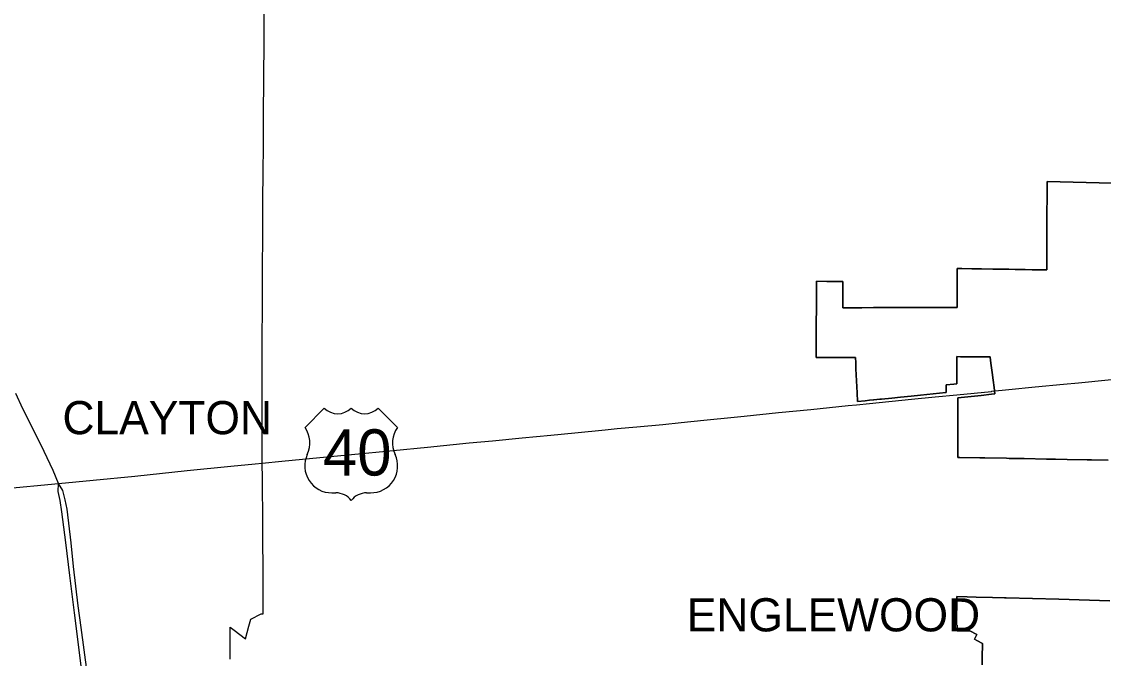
# Model space of a CAD drawing. Extents: x 0 to 34, y 0 to 22.
# Drawn here: x 4.4592 to 4.7212, y 15.7932 to 15.9476 of the extents above; entities that cross this region are included whole.
import ezdxf

# ---------------------------------------------------------------- set-up
doc = ezdxf.new("R2010")
doc.units = 0
for name, color, linetype in [('GM_X_Corporation', 7, 'Continuous'), ('GM_X_Corporation_Text', 7, 'Continuous'), ('GM_X_State_Route', 7, 'Continuous'), ('GM_X_US_Location', 7, 'Continuous'), ('GM_X_US_Route', 7, 'Continuous'), ('GM_X_US_Shield', 7, 'Continuous')]:
    doc.layers.add(name, color=color, linetype=linetype)

msp = doc.modelspace()

# ---------------------------------------------------------------- linework, layer by layer
at = {"layer": 'GM_X_Corporation'}
for points in [[(4.509726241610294, 15.793017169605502), (4.509716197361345, 15.794641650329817), (4.5097080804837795, 15.795954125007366), (4.509688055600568, 15.799192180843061), (4.509677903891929, 15.800833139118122), (4.510646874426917, 15.80009527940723), (4.513431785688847, 15.797974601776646), (4.5142712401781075, 15.801067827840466), (4.514736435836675, 15.802782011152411), (4.517228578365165, 15.80401493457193), (4.517710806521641, 15.804016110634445), (4.517710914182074, 15.804151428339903), (4.517709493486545, 15.804630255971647), (4.517699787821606, 15.807912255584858), (4.517699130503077, 15.808133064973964), (4.51769517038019, 15.809471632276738), (4.517673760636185, 15.81670944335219), (4.517672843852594, 15.817282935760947), (4.517672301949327, 15.81735647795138), (4.517655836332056, 15.819581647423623), (4.517641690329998, 15.821492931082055), (4.517636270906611, 15.822225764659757), (4.517621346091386, 15.82424240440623), (4.517612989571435, 15.82537208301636), (4.5175259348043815, 15.837136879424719), (4.517503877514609, 15.840117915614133), (4.5175002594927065, 15.840606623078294), (4.517500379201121, 15.840635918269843), (4.5174993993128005, 15.841239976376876), (4.517497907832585, 15.842158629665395), (4.517491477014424, 15.8461065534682), (4.517487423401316, 15.84860105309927), (4.517482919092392, 15.851368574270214), (4.517482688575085, 15.851509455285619), (4.51747875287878, 15.853929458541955), (4.517477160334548, 15.854908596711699), (4.517471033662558, 15.858674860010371), (4.517470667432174, 15.858895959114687), (4.517469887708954, 15.8593781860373), (4.517466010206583, 15.86175995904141), (4.517462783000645, 15.863741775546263), (4.517461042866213, 15.864812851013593), (4.517460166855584, 15.865350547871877), (4.5174602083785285, 15.865377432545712), (4.517460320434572, 15.865450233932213), (4.517471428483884, 15.86784446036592), (4.5174811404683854, 15.869938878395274), (4.517488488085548, 15.871521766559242), (4.5174935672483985, 15.872616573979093), (4.51749410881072, 15.872733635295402), (4.517510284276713, 15.876221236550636), (4.517529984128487, 15.880468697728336), (4.517545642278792, 15.883845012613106), (4.517554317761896, 15.88571430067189), (4.517559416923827, 15.886813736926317), (4.517563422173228, 15.887677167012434), (4.517563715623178, 15.887741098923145), (4.517564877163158, 15.88784580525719), (4.517565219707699, 15.887876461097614), (4.51756956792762, 15.888810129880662), (4.517576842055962, 15.89010945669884), (4.517594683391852, 15.893296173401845), (4.517647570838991, 15.902744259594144), (4.517652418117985, 15.903610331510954), (4.517655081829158, 15.904085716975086), (4.517671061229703, 15.906940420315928), (4.517678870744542, 15.908335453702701), (4.5177715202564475, 15.920094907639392), (4.517808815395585, 15.924827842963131), (4.517950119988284, 15.942761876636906), (4.517950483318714, 15.942916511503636), (4.517988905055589, 15.950246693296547)], [(4.722420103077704, 15.84125548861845), (4.718355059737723, 15.841334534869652), (4.717294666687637, 15.841355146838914), (4.712477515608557, 15.841448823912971), (4.712440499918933, 15.841449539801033), (4.709653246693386, 15.841503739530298), (4.707495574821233, 15.841545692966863), (4.702085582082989, 15.841650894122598), (4.700604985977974, 15.841679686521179), (4.699983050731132, 15.841691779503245), (4.698512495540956, 15.84172037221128), (4.698403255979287, 15.841722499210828), (4.697781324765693, 15.841734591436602), (4.6925126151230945, 15.841837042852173), (4.6913604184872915, 15.841859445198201), (4.686508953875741, 15.841953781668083), (4.685971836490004, 15.841964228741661), (4.685974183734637, 15.843864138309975), (4.68597219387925, 15.84422798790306), (4.685971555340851, 15.844343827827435), (4.685972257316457, 15.844765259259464), (4.685972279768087, 15.844779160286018), (4.685974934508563, 15.846386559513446), (4.685975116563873, 15.846473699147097), (4.6859806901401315, 15.84913856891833), (4.6859815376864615, 15.849827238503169), (4.6859852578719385, 15.852836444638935), (4.685988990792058, 15.855863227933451), (4.685989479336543, 15.856260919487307), (4.685989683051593, 15.8564212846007), (4.6916416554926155, 15.856988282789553), (4.694117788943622, 15.857236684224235), (4.694989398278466, 15.857324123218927), (4.694780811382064, 15.858918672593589), (4.694553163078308, 15.860658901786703), (4.694396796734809, 15.861854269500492), (4.694387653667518, 15.861924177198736), (4.694239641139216, 15.863055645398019), (4.6940840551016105, 15.864245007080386), (4.693927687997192, 15.865440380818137), (4.693812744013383, 15.866312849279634), (4.693705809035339, 15.866313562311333), (4.692894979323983, 15.866318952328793), (4.692775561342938, 15.866319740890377), (4.691689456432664, 15.866326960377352), (4.691570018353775, 15.86632775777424), (4.690907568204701, 15.866332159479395), (4.6900566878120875, 15.866337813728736), (4.689945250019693, 15.866338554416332), (4.689663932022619, 15.866340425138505), (4.689337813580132, 15.866342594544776), (4.686881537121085, 15.86635891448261), (4.686659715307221, 15.86636039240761), (4.685739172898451, 15.866377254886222), (4.685729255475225, 15.859781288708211), (4.685008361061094, 15.859708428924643), (4.683173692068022, 15.859523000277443), (4.683165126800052, 15.857913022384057), (4.683163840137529, 15.857670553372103), (4.683051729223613, 15.857659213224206), (4.676954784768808, 15.85704280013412), (4.6747094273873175, 15.856815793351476), (4.67469267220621, 15.856814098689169), (4.67212600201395, 15.856554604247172), (4.66999573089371, 15.856339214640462), (4.6675257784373, 15.856089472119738), (4.667136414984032, 15.856050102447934), (4.665617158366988, 15.855896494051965), (4.665609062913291, 15.855895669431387), (4.665607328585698, 15.855895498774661), (4.66559756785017, 15.855894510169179), (4.665587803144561, 15.855893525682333), (4.6655780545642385, 15.855892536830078), (4.664612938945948, 15.8557949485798), (4.664562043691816, 15.855789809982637), (4.663577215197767, 15.85569023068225), (4.663567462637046, 15.85568924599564), (4.663557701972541, 15.855688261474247), (4.663547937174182, 15.855687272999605), (4.66353816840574, 15.855686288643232), (4.661691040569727, 15.855499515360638), (4.661592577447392, 15.857578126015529), (4.661524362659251, 15.85902534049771), (4.6614560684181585, 15.86047419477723), (4.661454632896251, 15.860504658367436), (4.6613869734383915, 15.861940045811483), (4.661319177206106, 15.86337824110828), (4.6612506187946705, 15.864832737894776), (4.661186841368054, 15.866185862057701), (4.660272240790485, 15.866180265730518), (4.659840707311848, 15.866177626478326), (4.659466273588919, 15.866175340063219), (4.659070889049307, 15.866172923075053), (4.65794508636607, 15.866166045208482), (4.65714911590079, 15.866161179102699), (4.65668844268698, 15.866158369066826), (4.655402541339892, 15.866150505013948), (4.6536903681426, 15.866140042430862), (4.653088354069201, 15.866136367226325), (4.651654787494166, 15.866127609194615), (4.651662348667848, 15.867439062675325), (4.651676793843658, 15.869946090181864), (4.651678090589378, 15.870170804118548), (4.651684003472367, 15.871196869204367), (4.651698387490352, 15.873694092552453), (4.651706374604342, 15.875079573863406), (4.651711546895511, 15.875977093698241), (4.6517148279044, 15.876546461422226), (4.651723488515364, 15.878049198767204), (4.651730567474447, 15.879278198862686), (4.651736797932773, 15.880358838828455), (4.651741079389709, 15.8811019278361), (4.651743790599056, 15.881572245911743), (4.651752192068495, 15.883030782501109), (4.651755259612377, 15.883562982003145), (4.651761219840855, 15.88458774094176), (4.651761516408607, 15.884638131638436), (4.654242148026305, 15.884612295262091), (4.656624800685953, 15.884587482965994), (4.656946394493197, 15.88458413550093), (4.658161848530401, 15.884571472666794), (4.658148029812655, 15.882644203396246), (4.658144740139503, 15.882184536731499), (4.658133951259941, 15.880680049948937), (4.658121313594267, 15.87891677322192), (4.658116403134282, 15.878232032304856), (4.6583687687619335, 15.878232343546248), (4.661063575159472, 15.878235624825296), (4.661903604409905, 15.878236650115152), (4.662526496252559, 15.878237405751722), (4.662742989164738, 15.878237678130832), (4.6655903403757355, 15.878241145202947), (4.666466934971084, 15.878242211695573), (4.668127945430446, 15.878244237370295), (4.66940609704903, 15.878250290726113), (4.6720530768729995, 15.878262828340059), (4.673564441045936, 15.878269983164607), (4.673640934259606, 15.878270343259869), (4.674496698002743, 15.878274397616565), (4.6761505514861, 15.878279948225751), (4.677249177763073, 15.878283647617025), (4.677696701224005, 15.878285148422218), (4.679169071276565, 15.878290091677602), (4.6807055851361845, 15.878295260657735), (4.681147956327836, 15.878296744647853), (4.682150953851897, 15.878300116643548), (4.683435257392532, 15.878304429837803), (4.684993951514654, 15.878309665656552), (4.685816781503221, 15.878311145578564), (4.685800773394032, 15.887731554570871), (4.686604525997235, 15.887720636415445), (4.6869696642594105, 15.887714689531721), (4.689419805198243, 15.887674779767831), (4.689811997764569, 15.887668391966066), (4.6913536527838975, 15.887643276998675), (4.691750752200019, 15.887636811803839), (4.694475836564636, 15.887592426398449), (4.6948696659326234, 15.88758600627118), (4.697886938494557, 15.887536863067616), (4.698309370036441, 15.887529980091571), (4.699888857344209, 15.88750386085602), (4.7002981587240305, 15.887497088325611), (4.701899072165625, 15.887470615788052), (4.702307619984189, 15.887463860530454), (4.704012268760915, 15.887435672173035), (4.704424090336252, 15.887428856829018), (4.704816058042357, 15.887422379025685), (4.705227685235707, 15.887415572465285), (4.707558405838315, 15.88740632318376), (4.70758112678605, 15.89733271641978), (4.707635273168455, 15.908818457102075), (4.726492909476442, 15.90830667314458)], [(4.7264932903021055, 15.908306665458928), (4.707635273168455, 15.908818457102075), (4.70758112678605, 15.89733271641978), (4.707558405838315, 15.88740632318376), (4.707534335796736, 15.887406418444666), (4.705227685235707, 15.887415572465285), (4.704816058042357, 15.887422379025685), (4.704424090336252, 15.887428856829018), (4.704012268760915, 15.887435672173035), (4.702307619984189, 15.887463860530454), (4.701899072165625, 15.887470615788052), (4.7002981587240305, 15.887497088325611), (4.699888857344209, 15.88750386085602), (4.698309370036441, 15.887529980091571), (4.697886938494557, 15.887536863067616), (4.6948696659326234, 15.88758600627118), (4.694475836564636, 15.887592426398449), (4.691750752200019, 15.887636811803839), (4.6913536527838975, 15.887643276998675), (4.689811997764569, 15.887668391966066), (4.689419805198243, 15.887674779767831), (4.6869696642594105, 15.887714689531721), (4.686604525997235, 15.887720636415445), (4.68580076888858, 15.8877337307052), (4.685816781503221, 15.878311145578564), (4.684993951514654, 15.878309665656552), (4.683435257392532, 15.878304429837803), (4.682150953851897, 15.878300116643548), (4.681147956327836, 15.878296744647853), (4.6807055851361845, 15.878295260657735), (4.679169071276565, 15.878290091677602), (4.677696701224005, 15.878285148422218), (4.677249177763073, 15.878283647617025), (4.6761505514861, 15.878279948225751), (4.674496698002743, 15.878274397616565), (4.673640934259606, 15.878270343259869), (4.673564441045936, 15.878269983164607), (4.6720530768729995, 15.878262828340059), (4.66940609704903, 15.878250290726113), (4.668127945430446, 15.878244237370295), (4.666466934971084, 15.878242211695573), (4.6655903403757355, 15.878241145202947), (4.662742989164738, 15.878237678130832), (4.662526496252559, 15.878237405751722), (4.661903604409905, 15.878236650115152), (4.661063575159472, 15.878235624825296), (4.6583687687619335, 15.878232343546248), (4.658116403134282, 15.878232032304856), (4.658121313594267, 15.87891677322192), (4.658133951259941, 15.880680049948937), (4.658144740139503, 15.882184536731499), (4.658148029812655, 15.882644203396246), (4.658161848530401, 15.884571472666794), (4.656946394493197, 15.88458413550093), (4.656624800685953, 15.884587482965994), (4.654242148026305, 15.884612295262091), (4.651761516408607, 15.884638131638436), (4.651761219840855, 15.88458774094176), (4.651755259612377, 15.883562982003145), (4.651752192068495, 15.883030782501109), (4.651743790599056, 15.881572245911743), (4.651741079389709, 15.8811019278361), (4.651736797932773, 15.880358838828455), (4.651730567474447, 15.879278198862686), (4.651723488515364, 15.878049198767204), (4.6517148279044, 15.876546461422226), (4.651711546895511, 15.875977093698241), (4.651706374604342, 15.875079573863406), (4.651698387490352, 15.873694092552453), (4.651684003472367, 15.871196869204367), (4.651678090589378, 15.870170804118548), (4.651676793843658, 15.869946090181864), (4.651662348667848, 15.867439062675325), (4.651654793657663, 15.86612791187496), (4.653088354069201, 15.866136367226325), (4.6536903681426, 15.866140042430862), (4.655402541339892, 15.866150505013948), (4.65668844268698, 15.866158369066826), (4.65714911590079, 15.866161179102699), (4.65794508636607, 15.866166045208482), (4.659070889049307, 15.866172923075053), (4.659466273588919, 15.866175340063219), (4.659840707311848, 15.866177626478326), (4.660272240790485, 15.866180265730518), (4.661186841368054, 15.866185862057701), (4.6612506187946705, 15.864832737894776), (4.661319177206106, 15.86337824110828), (4.6613869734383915, 15.861940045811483), (4.6614560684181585, 15.86047419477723), (4.661524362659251, 15.85902534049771), (4.661592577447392, 15.857578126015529), (4.661690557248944, 15.855499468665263), (4.66353816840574, 15.855686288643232), (4.663547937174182, 15.855687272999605), (4.663557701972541, 15.855688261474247), (4.663567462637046, 15.85568924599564), (4.663577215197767, 15.85569023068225), (4.664562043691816, 15.855789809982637), (4.664612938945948, 15.8557949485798), (4.6655780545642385, 15.855892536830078), (4.665587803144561, 15.855893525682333), (4.66559756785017, 15.855894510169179), (4.665607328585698, 15.855895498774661), (4.665609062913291, 15.855895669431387), (4.665617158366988, 15.855896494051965), (4.667136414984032, 15.856050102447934), (4.6675257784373, 15.856089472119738), (4.66999573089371, 15.856339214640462), (4.67212600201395, 15.856554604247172), (4.67469267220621, 15.856814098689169), (4.6747094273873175, 15.856815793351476), (4.676954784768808, 15.85704280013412), (4.683051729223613, 15.857659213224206), (4.683163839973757, 15.857670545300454), (4.683165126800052, 15.857913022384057), (4.683173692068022, 15.859523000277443), (4.685008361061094, 15.859708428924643), (4.685729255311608, 15.859781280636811), (4.685738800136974, 15.866377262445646), (4.686659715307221, 15.86636039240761), (4.686881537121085, 15.86635891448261), (4.689337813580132, 15.866342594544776), (4.689663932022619, 15.866340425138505), (4.689945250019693, 15.866338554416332), (4.6900566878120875, 15.866337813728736), (4.690907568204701, 15.866332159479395), (4.691570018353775, 15.86632775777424), (4.691689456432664, 15.866326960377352), (4.692775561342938, 15.866319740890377), (4.692894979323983, 15.866318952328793), (4.693705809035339, 15.866313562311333), (4.693812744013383, 15.866312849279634), (4.693927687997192, 15.865440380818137), (4.694083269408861, 15.864251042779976), (4.694239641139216, 15.863055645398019), (4.694387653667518, 15.861924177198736), (4.694396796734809, 15.861854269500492), (4.694553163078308, 15.860658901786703), (4.694781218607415, 15.858915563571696), (4.694989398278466, 15.857324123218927), (4.694117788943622, 15.857236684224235), (4.6916416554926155, 15.856988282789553), (4.685989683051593, 15.8564212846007), (4.685989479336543, 15.856260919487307), (4.685988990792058, 15.855863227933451), (4.6859852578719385, 15.852836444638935), (4.6859815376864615, 15.849827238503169), (4.6859806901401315, 15.84913856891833), (4.685975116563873, 15.846473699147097), (4.685974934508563, 15.846386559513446), (4.685972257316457, 15.844765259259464), (4.685971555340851, 15.844343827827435), (4.68597219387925, 15.84422798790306), (4.685974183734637, 15.843864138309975), (4.685971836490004, 15.841964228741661), (4.686508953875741, 15.841953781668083), (4.6913604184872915, 15.841859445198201), (4.6925126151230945, 15.841837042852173), (4.697781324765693, 15.841734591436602), (4.698403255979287, 15.841722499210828), (4.698512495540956, 15.84172037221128), (4.699983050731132, 15.841691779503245), (4.700604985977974, 15.841679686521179), (4.702085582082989, 15.841650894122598), (4.707495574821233, 15.841545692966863), (4.709653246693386, 15.841503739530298), (4.712440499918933, 15.841449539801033), (4.712477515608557, 15.841448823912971), (4.717294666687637, 15.841355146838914), (4.718355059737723, 15.841334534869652), (4.722420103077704, 15.84125548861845)], [(4.691918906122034, 15.791652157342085), (4.691925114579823, 15.79339569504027), (4.691937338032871, 15.796827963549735), (4.690605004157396, 15.797567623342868), (4.690024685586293, 15.797889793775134), (4.69000357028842, 15.797901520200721), (4.6901109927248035, 15.798095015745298), (4.690610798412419, 15.798995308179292), (4.6889374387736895, 15.79992429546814), (4.685822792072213, 15.799935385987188), (4.685817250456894, 15.799935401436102), (4.6858239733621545, 15.801202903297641), (4.685824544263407, 15.801310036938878), (4.685687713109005, 15.801310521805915), (4.685710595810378, 15.80823819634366), (4.685768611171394, 15.808236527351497), (4.688229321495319, 15.808165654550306), (4.69041016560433, 15.808102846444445), (4.694375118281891, 15.807988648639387), (4.697277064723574, 15.807905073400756), (4.697708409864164, 15.80789265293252), (4.710497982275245, 15.807563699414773), (4.722801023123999, 15.807224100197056)], [(4.722801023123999, 15.807224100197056), (4.710497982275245, 15.807563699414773), (4.697708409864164, 15.80789265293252), (4.697277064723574, 15.807905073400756), (4.694375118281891, 15.807988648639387), (4.69041016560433, 15.808102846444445), (4.688229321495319, 15.808165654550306), (4.685768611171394, 15.808236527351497), (4.685710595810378, 15.80823819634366), (4.685687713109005, 15.801310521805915), (4.685824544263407, 15.801310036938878), (4.6858239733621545, 15.801202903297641), (4.685822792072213, 15.799935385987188), (4.6889374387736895, 15.79992429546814), (4.690610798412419, 15.798995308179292), (4.6901109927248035, 15.798095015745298), (4.69000357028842, 15.797901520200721), (4.690024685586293, 15.797889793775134), (4.690605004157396, 15.797567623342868), (4.691937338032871, 15.796827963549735), (4.691925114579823, 15.79339569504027), (4.691918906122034, 15.791652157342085)]]:
    msp.add_lwpolyline(points, dxfattribs=at)
at = {"layer": 'GM_X_State_Route'}
for points in [[(4.468133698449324, 15.835663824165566), (4.466839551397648, 15.83881586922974), (4.464678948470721, 15.843343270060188), (4.46222460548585, 15.84828202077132), (4.459494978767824, 15.853718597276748), (4.45781691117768, 15.857410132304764)], [(4.475811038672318, 15.779177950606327), (4.475047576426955, 15.782024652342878), (4.474396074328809, 15.785356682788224), (4.473949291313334, 15.788800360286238), (4.4726835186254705, 15.799187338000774), (4.4720320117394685, 15.804269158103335), (4.470859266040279, 15.813353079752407), (4.46987272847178, 15.821320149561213), (4.468904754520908, 15.828728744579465), (4.4685040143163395, 15.83151596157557), (4.468037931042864, 15.833722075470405), (4.468133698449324, 15.835663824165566)], [(4.483026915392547, 15.768156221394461), (4.482546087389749, 15.768737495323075), (4.480759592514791, 15.771381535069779), (4.479258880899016, 15.773989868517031), (4.47815126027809, 15.776240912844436), (4.477007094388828, 15.779174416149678), (4.476257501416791, 15.781922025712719), (4.475685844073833, 15.7850663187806), (4.475042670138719, 15.789925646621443), (4.473649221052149, 15.80075202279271), (4.472934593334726, 15.805968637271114), (4.471755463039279, 15.8155086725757), (4.47121296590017, 15.821245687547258), (4.470219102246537, 15.829407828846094), (4.469754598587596, 15.83165887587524), (4.469147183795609, 15.833945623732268), (4.468133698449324, 15.835663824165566)]]:
    msp.add_lwpolyline(points, dxfattribs=at)
at = {"layer": 'GM_X_US_Route'}
for p, q in [((4.685730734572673, 15.85709582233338), (4.694137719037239, 15.857957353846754)), ((4.515808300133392, 15.840373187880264), (4.51744839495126, 15.840535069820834))]:
    msp.add_line(p, q, dxfattribs=at)
for points in [[(4.698342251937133, 15.858383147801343), (4.704733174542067, 15.85903018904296), (4.711560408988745, 15.859704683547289), (4.715233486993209, 15.860055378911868), (4.72239822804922, 15.86078208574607), (4.728784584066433, 15.861366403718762), (4.730382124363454, 15.861545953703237)], [(4.661436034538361, 15.854710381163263), (4.664586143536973, 15.855032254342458), (4.674762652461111, 15.856096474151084), (4.680538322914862, 15.856654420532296), (4.685730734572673, 15.85709582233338)], [(4.694137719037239, 15.857957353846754), (4.694221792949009, 15.857965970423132), (4.698342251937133, 15.858383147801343)], [(4.634270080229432, 15.851964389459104), (4.642575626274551, 15.852832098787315), (4.650346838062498, 15.853568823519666), (4.659455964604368, 15.854508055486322), (4.661436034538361, 15.854710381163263)], [(4.51744839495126, 15.840535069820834), (4.522253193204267, 15.841018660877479), (4.531409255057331, 15.841923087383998), (4.53911349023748, 15.842648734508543), (4.5492304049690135, 15.84365758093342), (4.5574830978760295, 15.844452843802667), (4.567613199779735, 15.8454437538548), (4.5732918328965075, 15.84597217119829), (4.580457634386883, 15.846658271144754), (4.587427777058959, 15.84732696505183), (4.593234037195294, 15.847907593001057), (4.600558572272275, 15.84863376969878), (4.603460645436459, 15.84891432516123), (4.608196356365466, 15.849392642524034), (4.614549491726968, 15.849962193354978), (4.618959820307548, 15.850442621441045), (4.624453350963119, 15.850989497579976), (4.631778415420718, 15.851704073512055), (4.634270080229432, 15.851964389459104)], [(4.468133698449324, 15.835663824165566), (4.476496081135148, 15.836462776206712), (4.486612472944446, 15.837434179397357), (4.499307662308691, 15.838740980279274), (4.509903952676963, 15.839790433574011), (4.515808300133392, 15.840373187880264)], [(4.454499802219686, 15.834296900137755), (4.468133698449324, 15.835663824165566)]]:
    msp.add_lwpolyline(points, dxfattribs=at)
at = {"layer": 'GM_X_US_Shield'}
for p, q in [((4.532515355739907, 15.853874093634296), (4.5278532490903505, 15.849211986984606)), ((4.550231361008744, 15.849211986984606), (4.545569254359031, 15.853874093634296)), ((4.534380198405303, 15.833360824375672), (4.535312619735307, 15.833360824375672)), ((4.542771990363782, 15.833360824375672), (4.543704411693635, 15.833360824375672))]:
    msp.add_line(p, q, dxfattribs=at)
for centre, radius, start, end in [((4.535778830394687, 15.85720350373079), 0.004662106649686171, 225.57299599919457, 314.4270040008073), ((4.542305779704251, 15.85720350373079), 0.004662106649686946, 225.57299599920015, 314.4270040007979), ((4.522506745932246, 15.845468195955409), 0.006526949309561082, 334.5471236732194, 35.000929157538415), ((4.555577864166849, 15.845468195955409), 0.006526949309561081, 144.99907084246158, 205.4528763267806), ((4.534307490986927, 15.839887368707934), 0.006526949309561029, 154.8319194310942, 270.63826363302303), ((4.543777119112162, 15.839887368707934), 0.006526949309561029, 269.36173636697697, 25.168080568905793), ((4.535312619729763, 15.828698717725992), 0.0046621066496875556, 36.86989764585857, 89.99999993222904), ((4.542771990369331, 15.828698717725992), 0.0046621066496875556, 90.00000006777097, 143.13010235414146)]:
    msp.add_arc(centre, radius, start, end, dxfattribs=at)

# ---------------------------------------------------------------- texts
at = {"layer": 'GM_X_Corporation_Text'}
for s, p in [('CLAYTON', (4.4690933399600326, 15.847567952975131)), ('ENGLEWOOD', (4.620326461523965, 15.79978383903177))]:
    msp.add_text(s, height=0.008037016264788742, rotation=1.0000000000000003e-05, dxfattribs=at).set_placement(p)
at = {"layer": 'GM_X_US_Location'}
for s, p in [('0', (4.53903618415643, 15.843063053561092)), ('/', (4.539037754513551, 15.843063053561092))]:
    msp.add_text(s, height=1.6074032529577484e-05, dxfattribs=at).set_placement(p)
msp.add_text('40', height=1.6074032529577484e-05, rotation=1.0000000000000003e-05, dxfattribs=at).set_placement((4.5357183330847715, 15.839735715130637))
at = {"layer": 'GM_X_US_Shield'}
msp.add_text('40', height=0.011189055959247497, dxfattribs=at).set_placement((4.532176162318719, 15.837556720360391))

doc.saveas('drawing.dxf')
